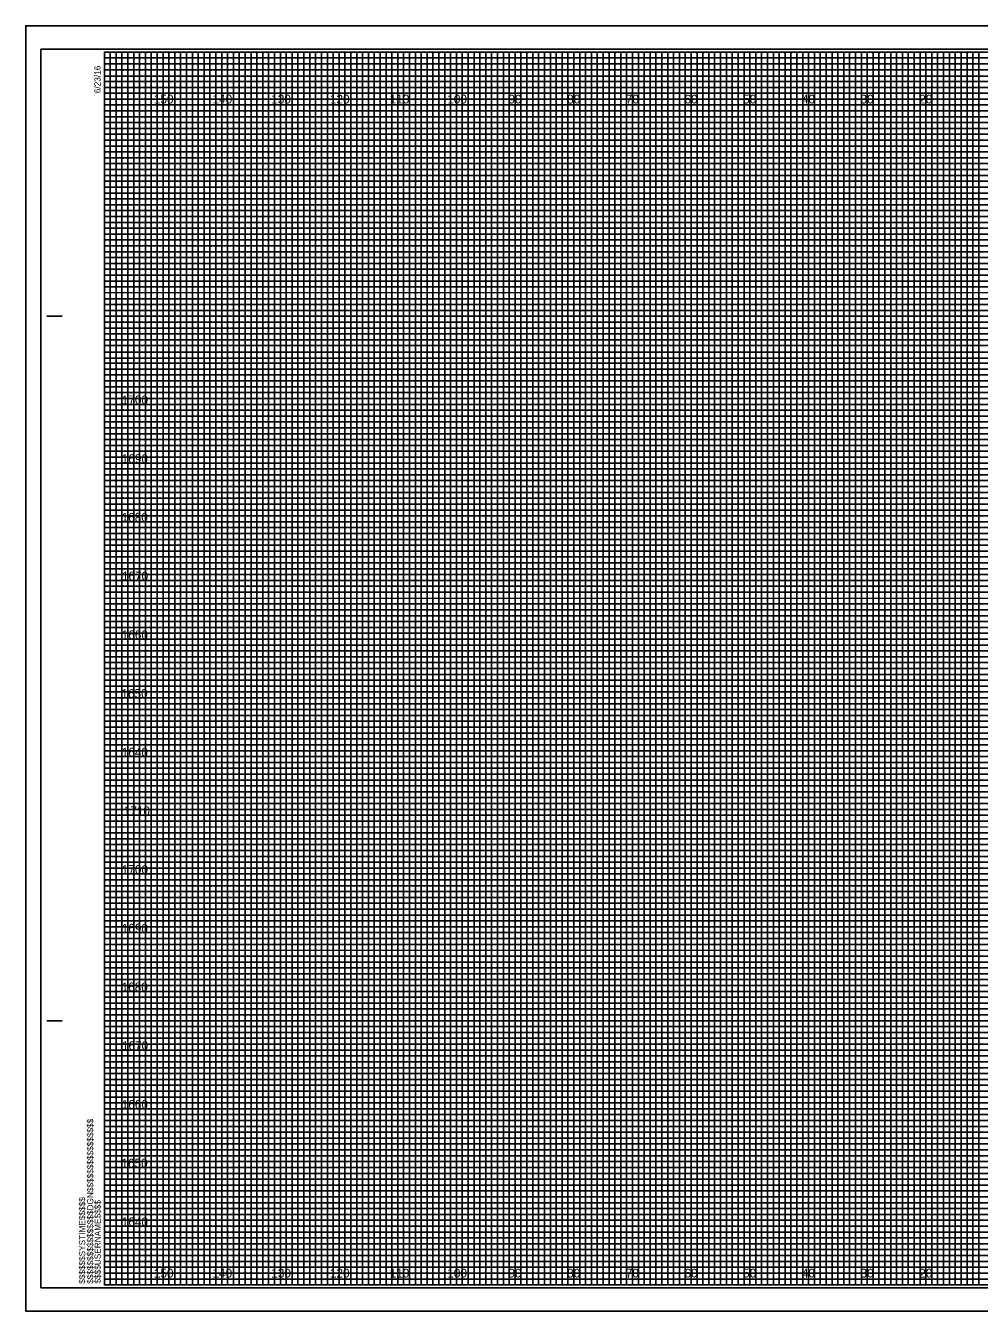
# Model space of a CAD drawing. Extents: x -13 to 323, y -5 to 2414.
# Drawn here: x -13.4 to 149.1, y 435.5 to 654.5 of the extents above; entities that cross this region are included whole.
import ezdxf

# ---------------------------------------------------------------- set-up
doc = ezdxf.new("R2010")
doc.units = 0
for name, color, linetype in [('Prop XS Elevation Labels', 7, 'Continuous'), ('Prop XS Offset Labels', 7, 'Continuous'), ('Sheet Cross Section CELL', 7, 'Continuous'), ('Sheet Cross Section Grid Major CELL', 7, 'Continuous'), ('Sheet Cross Section Grid Middle CELL', 7, 'Continuous'), ('Sheet Cross Section Grid Minor 1 CELL', 7, 'Continuous'), ('Sheet Cross Section Grid Minor 2 CELL', 7, 'Continuous'), ('Sheet Cutting Line CELL', 7, 'Continuous'), ('Sheet DOT Grid CELL', 7, 'Continuous'), ('Sheet Plot Border Inside CELL', 7, 'Continuous'), ('Sheet Plot Border Outside CELL', 7, 'Continuous')]:
    doc.layers.add(name, color=color, linetype=linetype)

msp = doc.modelspace()

# ---------------------------------------------------------------- linework, layer by layer
at = {"layer": 'Sheet Cross Section CELL'}
for p, q in [((-9.8, 605), (-7.3, 605)), ((-9.7, 605), (-7.2, 605)), ((-9.8, 485), (-7.3, 485)), ((-9.7, 485), (-7.2, 485)), ((0, 440), (0, 440)), ((0, 440), (0, 440)), ((0, 440), (0, 440)), ((0, 440), (0, 440)), ((0, 440), (0, 440)), ((0, 440), (0, 440)), ((0, 440), (0, 440))]:
    msp.add_line(p, q, dxfattribs=at)
msp.add_lwpolyline([(320, 650), (0, 650), (0, 440), (320, 440)], close=True, dxfattribs=at)
at = {"layer": 'Sheet Cross Section Grid Major CELL'}
for p, q in [((10, 650), (0, 650)), ((10, 440), (10, 650)), ((30, 650), (20, 650)), ((20, 650), (20, 440)), ((30, 440), (30, 650)), ((50, 650), (40, 650)), ((40, 650), (40, 440)), ((50, 440), (50, 650)), ((70, 650), (60, 650)), ((60, 650), (60, 440)), ((70, 440), (70, 650)), ((90, 650), (80, 650)), ((80, 650), (80, 440)), ((90, 440), (90, 650)), ((110, 650), (100, 650)), ((100, 650), (100, 440)), ((110, 440), (110, 650)), ((130, 650), (120, 650)), ((120, 650), (120, 440)), ((130, 440), (130, 650)), ((150, 650), (140, 650)), ((140, 650), (140, 440)), ((20, 440), (10, 440)), ((40, 440), (30, 440)), ((60, 440), (50, 440)), ((80, 440), (70, 440)), ((100, 440), (90, 440)), ((120, 440), (110, 440)), ((140, 440), (130, 440))]:
    msp.add_line(p, q, dxfattribs=at)
for points in [[(0, 640), (320, 640), (320, 630), (0, 630)], [(0, 620), (320, 620), (320, 610), (0, 610)], [(0, 600), (320, 600), (320, 590), (0, 590)], [(0, 580), (320, 580), (320, 570), (0, 570)], [(0, 560), (320, 560), (320, 550), (0, 550)], [(0, 540), (320, 540), (320, 530), (0, 530)], [(0, 520), (320, 520), (320, 510), (0, 510)], [(0, 500), (320, 500), (320, 490), (0, 490)], [(0, 480), (320, 480), (320, 470), (0, 470)], [(0, 460), (320, 460), (320, 450), (0, 450)]]:
    msp.add_lwpolyline(points, dxfattribs=at)
at = {"layer": 'Sheet Cross Section Grid Middle CELL'}
for points in [[(0, 650), (5, 650), (5, 440), (15, 440), (15, 650), (25, 650), (25, 440), (35, 440), (35, 650), (45, 650), (45, 440), (55, 440), (55, 650), (65, 650), (65, 440), (75, 440), (75, 650), (85, 650), (85, 440), (95, 440), (95, 650), (105, 650), (105, 440), (115, 440), (115, 650), (125, 650), (125, 440), (135, 440), (135, 650), (145, 650), (145, 440), (155, 440)], [(0, 645), (275, 645)], [(0, 625), (320, 625), (320, 635), (0, 635)], [(0, 605), (320, 605), (320, 615), (0, 615)], [(0, 585), (320, 585), (320, 595), (0, 595)], [(0, 565), (320, 565), (320, 575), (0, 575)], [(0, 545), (320, 545), (320, 555), (0, 555)], [(0, 525), (320, 525), (320, 535), (0, 535)], [(0, 505), (320, 505), (320, 515), (0, 515)], [(0, 485), (320, 485), (320, 495), (0, 495)], [(0, 465), (320, 465), (320, 475), (0, 475)], [(0, 445), (320, 445), (320, 455), (0, 455)]]:
    msp.add_lwpolyline(points, dxfattribs=at)
at = {"layer": 'Sheet Cross Section Grid Minor 1 CELL'}
for p, q in [((0, 649), (260, 649)), ((260, 647.98), (0, 647.98)), ((0, 647.98), (0, 647)), ((0, 647), (260, 647)), ((260, 645.89), (0, 645.89)), ((0, 645.89), (0, 644)), ((0, 644), (320, 644))]:
    msp.add_line(p, q, dxfattribs=at)
for points in [[(0, 643), (270, 643), (320, 643), (320, 642), (0, 642)], [(0, 641), (320, 641), (320, 639), (0, 639)], [(0, 638), (320, 638), (320, 637), (0, 636.98)], [(0, 636), (320, 636), (320, 634), (0, 634)], [(0, 633), (320, 633), (320, 632), (0, 632)], [(0, 631), (320, 631), (320, 629), (0, 629)], [(0, 628), (320, 628), (320, 627), (0, 627)], [(0, 626), (320, 626), (320, 624), (0, 624)], [(0, 623), (320, 623), (320, 622), (0, 622)], [(0, 621), (320, 621), (320, 619), (0, 619)], [(0, 618), (320, 618), (320, 617), (0, 617)], [(0, 616), (320, 616), (320, 613.95), (320, 613), (320, 612), (0, 612)], [(0, 614), (320, 614), (320, 613), (0, 613)], [(0, 611), (320, 611), (320, 609), (0, 609.03)], [(0, 609.03), (320, 609), (320, 608), (0, 608)], [(0, 607), (320, 607), (320, 606), (0, 606)], [(0, 604), (320, 604), (320, 603), (0, 603)], [(0, 602), (320, 602), (320, 601), (0, 601)], [(-0.07, 598.89), (320, 598.89), (320, 597.88), (-0.07, 597.88)], [(0, 597), (320, 597), (320, 596), (0, 596)], [(0, 594), (320, 594), (320, 593), (0, 593)], [(0, 592), (320, 592), (320, 591), (0, 591)], [(0, 589), (320, 589), (320, 588), (0, 588)], [(0, 587), (320, 587), (320, 586), (0, 586)], [(0, 584), (320, 584), (320, 583), (0, 583)], [(0, 582), (320, 582), (320, 581), (0, 581)], [(0, 579), (320, 579), (319.99, 577.98), (0, 578)], [(0, 577), (320, 577), (320, 576), (0, 576)], [(0, 574), (320, 574), (320, 573), (0, 573)], [(0, 572), (320, 572), (320, 571), (0, 571)], [(0, 569), (320, 569), (320, 568), (0, 568)], [(0, 567), (320, 567), (320, 566), (0, 566)], [(0, 564), (320, 564), (320, 563), (0, 563)], [(0, 562), (320, 562), (320, 561), (0, 561)], [(0, 559), (320, 559), (320, 558), (0, 558)], [(0, 556.99), (320.07, 556.91), (320, 556), (0, 556)], [(0, 554), (320, 554), (320, 553), (0, 553)], [(0, 552), (320, 552), (320, 551), (0, 551)], [(0, 549), (320, 549), (320, 548), (0, 548)], [(0, 547), (320, 547), (320, 546), (0, 546)], [(0, 544), (320, 544), (320, 543), (0, 543)], [(0, 542), (320, 542), (320, 541), (0, 541)], [(0, 539), (320, 539), (320, 538), (0, 538)], [(0, 537), (320, 537), (320, 536), (0, 536)], [(0, 534), (320, 534), (320, 533), (0, 533)], [(0, 532), (320, 532), (320, 531), (0, 531)], [(0, 529), (320, 529), (320, 528), (0, 528)], [(0, 527), (320, 527), (320, 526), (0, 526)], [(0, 524), (320, 524), (320, 523), (0, 523)], [(0, 522), (320, 522), (320, 521), (0, 521)], [(0, 519), (320, 519), (319.99, 517.98), (0, 518)], [(0, 517), (320, 517), (320, 516), (0, 516)], [(0, 514), (320, 514), (320, 513), (0, 513)], [(0, 512), (320, 512), (320, 511), (0, 511)], [(0, 509), (320, 509), (320, 508), (0, 508)], [(0, 507), (320, 507), (320, 506), (0, 506)], [(0, 504), (320, 504), (320, 503), (0, 503)], [(0, 502), (320, 502), (320, 501), (0, 501)], [(0, 499), (320, 499), (320, 498), (0, 498)], [(0, 496.99), (320.07, 496.91), (320, 496), (0, 496)], [(0, 494), (320, 494), (320, 493), (0, 493)], [(0, 492), (320, 492), (320, 491), (0, 491)], [(0, 489), (320, 489), (320, 488), (0, 488)], [(0, 487), (320, 487), (320, 486), (0, 486)], [(0, 484), (320, 484), (320, 483), (0, 483)], [(0, 482), (320, 482), (320, 481), (0, 481)], [(0, 479), (320, 479), (320, 478), (0, 478)], [(0, 477), (320, 477), (320, 476), (0, 476)], [(0, 474), (320, 474), (320, 473), (0, 473)], [(0, 472), (320, 472), (320, 471), (0, 471)], [(0, 469), (320, 469), (320, 468), (0, 468)], [(0, 467), (320, 467), (320, 466), (0, 466)], [(0, 464), (320, 464), (320, 463), (0, 463)], [(0, 462), (320, 462), (320, 461), (0, 461)], [(0, 459), (320, 459), (320, 458), (0, 458)], [(0, 457), (320, 457), (320, 456), (0, 456)], [(0, 454), (320, 454), (320, 453), (0, 453)], [(0, 452), (320, 452), (320, 451), (0, 451)], [(0, 449), (320, 449), (320, 448), (0, 448)], [(0, 447), (320, 447), (320, 446), (0, 446)], [(0, 444), (320, 444), (320, 443), (0, 443)], [(0, 442), (320, 442), (320, 441), (0, 441)]]:
    msp.add_lwpolyline(points, dxfattribs=at)
at = {"layer": 'Sheet Cross Section Grid Minor 2 CELL'}
for points in [[(0, 440), (1, 440), (1, 650), (2, 650), (2, 440)], [(2, 440), (3, 440), (3, 650), (4, 650), (4, 440)], [(5, 440), (6, 440), (6, 650), (7, 650), (7, 440)], [(7, 440), (8, 440), (8, 650), (9, 650), (9, 440)], [(10, 440), (11, 440), (11, 650), (12, 650), (12, 440)], [(12, 440), (13, 440), (13, 650), (14, 650), (14, 440)], [(15, 440), (16, 440), (16, 650), (17, 650), (17, 440)], [(17, 440), (18, 440), (18, 650), (19, 650), (19, 440)], [(20, 440), (21, 440), (21, 650), (22, 650), (22, 440)], [(22, 440), (23, 440), (23, 650), (24, 650), (24, 440)], [(25, 440), (26, 440), (26, 650), (27, 650), (27, 440)], [(27, 440), (28, 440), (28, 650), (29, 650), (29, 440)], [(30, 440), (31, 440), (31, 650), (32, 650), (32, 440)], [(32, 440), (33, 440), (33, 650), (34, 650), (34, 440)], [(35, 440), (36, 440), (36, 650), (37, 650), (37, 440)], [(37, 440), (38, 440), (38, 650), (39, 650), (39, 440)], [(40, 440), (41, 440), (41, 650), (42, 650), (42, 440)], [(42, 440), (43, 440), (43, 650), (44, 650), (44, 440)], [(45, 440), (46, 440), (46, 650), (47, 650), (47, 440)], [(47, 440), (48, 440), (48, 650), (49, 650), (49, 440)], [(50, 440), (51, 440), (51, 650), (52, 650), (52, 440)], [(52, 440), (53, 440), (53, 650), (54, 650), (54, 440)], [(55, 440), (56, 440), (56, 650), (57, 650), (57, 440)], [(57, 440), (58, 440), (58, 650), (59, 650), (59, 440)], [(60, 440), (61, 440), (61, 650), (62, 650), (62, 440)], [(62, 440), (63, 440), (63, 650), (64, 650), (64, 440)], [(65, 440), (66, 440), (66, 650), (67, 650), (67, 440)], [(67, 440), (68, 440), (68, 650), (69, 650), (69, 440)], [(70, 440), (71, 440), (71, 650), (72, 650), (72, 440)], [(72, 440), (73, 440), (73, 650), (74, 650), (74, 440)], [(75, 440), (76, 440), (76, 650), (77, 650), (77, 440)], [(77, 440), (78, 440), (78, 650), (79, 650), (79, 440)], [(80, 440), (81, 440), (81, 650), (82, 650), (82, 440)], [(82, 440), (83, 440), (83, 650), (84, 650), (84, 440)], [(85, 440), (86, 440), (86, 650), (87, 650), (87, 440)], [(87, 440), (88, 440), (88, 650), (89, 650), (89, 440)], [(90, 440), (91, 440), (91, 650), (92, 650), (92, 440)], [(92, 440), (93, 440), (93, 650), (94, 650), (94, 440)], [(95, 440), (96, 440), (96, 650), (97, 650), (97, 440)], [(97, 440), (98, 440), (98, 650), (99, 650), (99, 440)], [(100, 440), (101, 440), (101, 650), (102, 650), (102, 440)], [(102, 440), (103, 440), (103, 650), (104, 650), (104, 440)], [(105, 440), (106, 440), (106, 650), (107, 650), (107, 440)], [(107, 440), (108, 440), (108, 650), (109, 650), (109, 440)], [(110, 440), (111, 440), (111, 650), (112, 650), (112, 440)], [(112, 440), (113, 440), (113, 650), (114, 650), (114, 440)], [(115, 440), (116, 440), (116, 650), (117, 650), (117, 440)], [(117, 440), (118, 440), (118, 650), (119, 650), (119, 440)], [(120, 440), (121, 440), (121, 650), (122, 650), (122, 440)], [(122, 440), (123, 440), (123, 650), (124, 650), (124, 440)], [(125, 440), (126, 440), (126, 650), (127, 650), (127, 440)], [(127, 440), (128, 440), (128, 650), (129, 650), (129, 440)], [(130, 440), (131, 440), (131, 650), (132, 650), (132, 440)], [(132, 440), (133, 440), (133, 650), (134, 650), (134, 440)], [(135, 440), (136, 440), (136, 650), (137, 650), (137, 440)], [(137, 440), (138, 440), (138, 650), (139, 650), (139, 440)], [(140, 440), (141, 440), (141, 650), (142, 650), (142, 440)], [(142, 440), (143, 440), (143, 650), (144, 650), (144, 440)], [(145, 440), (146, 440), (146, 650), (147, 650), (147, 440)], [(147, 440), (148, 440), (148, 650), (149, 650), (149, 440)]]:
    msp.add_lwpolyline(points, dxfattribs=at)
at = {"layer": 'Sheet Cutting Line CELL'}
for p, q in [((323.3, 654.5), (-13.4, 654.5)), ((-13.4, 654.5), (-13.4, 435.5)), ((-13.4, 435.5), (323.3, 435.5))]:
    msp.add_line(p, q, dxfattribs=at)
at = {"layer": 'Sheet DOT Grid CELL'}
for p, q in [((10, 440), (10, 650)), ((20, 440), (20, 650)), ((30, 440), (30, 650)), ((40, 440), (40, 650)), ((50, 440), (50, 650)), ((60, 440), (60, 650)), ((70, 440), (70, 650)), ((80, 440), (80, 650)), ((90, 440), (90, 650)), ((100, 440), (100, 650)), ((110, 440), (110, 650)), ((120, 440), (120, 650)), ((130, 440), (130, 650)), ((140, 440), (140, 650)), ((0, 640), (320, 640)), ((0, 630), (320, 630)), ((0, 620), (320, 620)), ((0, 610), (320, 610)), ((0, 600), (320, 600)), ((0, 590), (320, 590)), ((0, 580), (320, 580)), ((0, 570), (320, 570)), ((0, 560), (320, 560)), ((0, 550), (320, 550)), ((0, 540), (320, 540)), ((0, 530), (320, 530)), ((0, 520), (320, 520)), ((0, 510), (320, 510)), ((0, 500), (320, 500)), ((0, 490), (320, 490)), ((0, 480), (320, 480)), ((0, 470), (320, 470)), ((0, 460), (320, 460)), ((0, 450), (320, 450))]:
    msp.add_line(p, q, dxfattribs=at)
at = {"layer": 'Sheet Plot Border Inside CELL'}
msp.add_lwpolyline([(-10.8, 439.5), (322.4, 439.5), (322.4, 650.5), (-10.8, 650.5)], close=True, dxfattribs=at)
at = {"layer": 'Sheet Plot Border Outside CELL'}
msp.add_lwpolyline([(-13.4, 435.5), (323.3, 435.5), (323.3, 654.5), (-13.4, 654.5)], close=True, dxfattribs=at)

# ---------------------------------------------------------------- texts
at = {"layer": 'Prop XS Elevation Labels'}
for s, p in [('1700', (2.98, 590)), ('1690', (2.97, 580)), ('1680', (2.95, 570)), ('1670', (3, 560)), ('1660', (2.97, 550)), ('1650', (2.92, 540)), ('1640', (2.97, 530)), ('1710', (3.31, 520)), ('1700', (2.98, 510)), ('1690', (2.97, 500)), ('1680', (2.95, 490)), ('1670', (3, 480)), ('1660', (2.97, 470)), ('1650', (2.92, 460)), ('1640', (2.97, 450))]:
    msp.add_text(s, height=1.5, dxfattribs=at).set_placement(p)
at = {"layer": 'Prop XS Offset Labels'}
for s, p in [('150', (8.44, 641.25)), ('140', (18.44, 641.25)), ('130', (28.44, 641.25)), ('120', (38.44, 641.25)), ('110', (48.62, 641.25)), ('100', (58.44, 641.25)), ('90', (68.86, 641.25)), ('80', (78.86, 641.25)), ('70', (88.86, 641.25)), ('60', (98.86, 641.25)), ('50', (108.86, 641.25)), ('40', (118.86, 641.25)), ('30', (128.86, 641.25)), ('20', (138.86, 641.25)), ('150', (8.44, 441.25)), ('140', (18.44, 441.25)), ('130', (28.44, 441.25)), ('120', (38.44, 441.25)), ('110', (48.62, 441.25)), ('100', (58.44, 441.25)), ('90', (68.86, 441.25)), ('80', (78.86, 441.25)), ('70', (88.86, 441.25)), ('60', (98.86, 441.25)), ('50', (108.86, 441.25)), ('40', (118.86, 441.25)), ('30', (128.86, 441.25)), ('20', (138.86, 441.25))]:
    msp.add_text(s, height=1.5, dxfattribs=at).set_placement(p)
at = {"layer": 'Sheet Cross Section CELL'}
for s, p in [('6/23/16', (-0.65, 643)), ('$$$$$$$$$$$$$$$$DGN$$$$$$$$$$$$$$$$', (-1.88, 440.18)), ('$$$$$$SYSTIME$$$$$', (-3.26, 440.18)), ('$$$$USERNAME$$$$', (-0.62, 440.23))]:
    msp.add_text(s, height=1.05, rotation=90, dxfattribs=at).set_placement(p)

doc.saveas('drawing.dxf')
